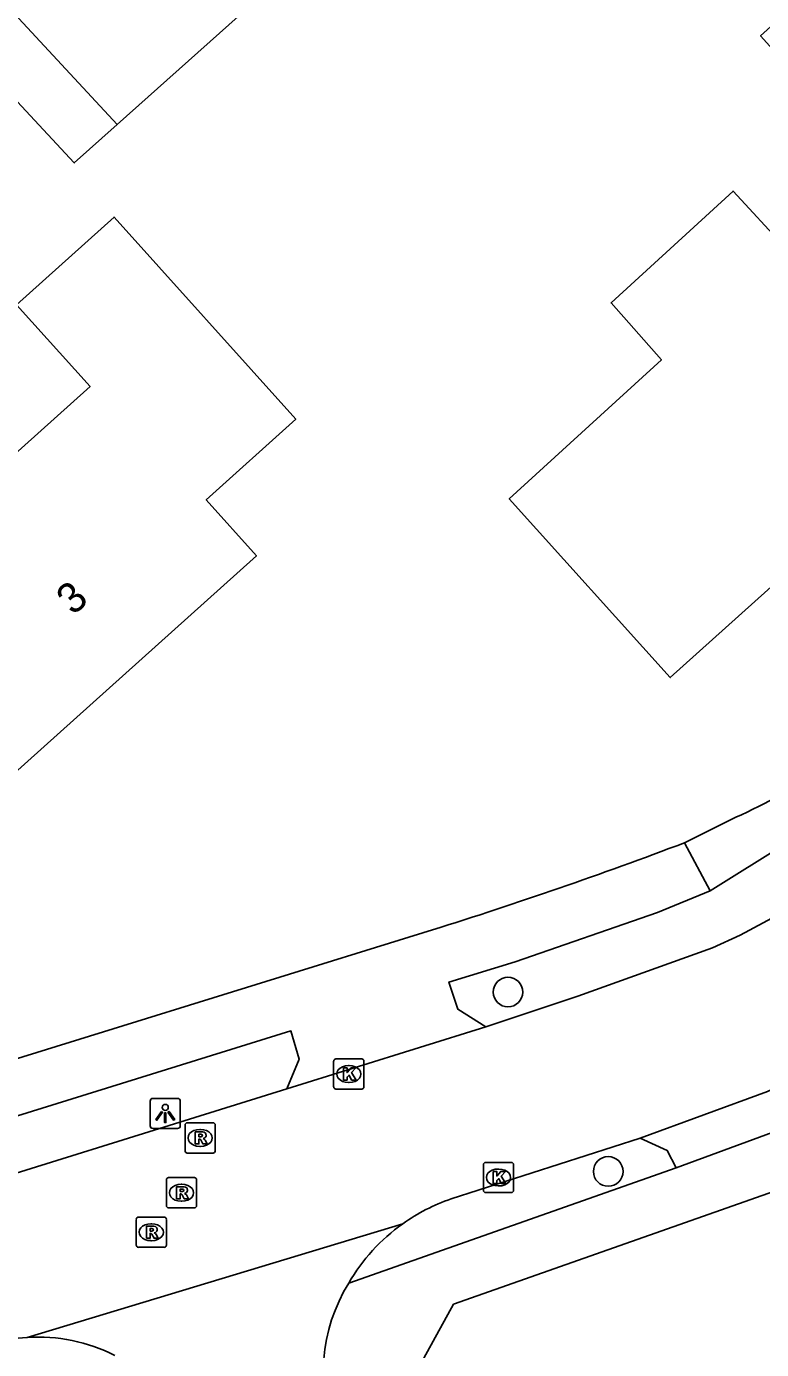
# Model space of a CAD drawing. Extents: x 163268 to 164360, y 381529 to 382285.
# Drawn here: x 163878.84 to 163903.13, y 381641.5 to 381685.27 of the extents above; entities that cross this region are included whole.
import ezdxf

# ---------------------------------------------------------------- set-up
doc = ezdxf.new("R2010")
doc.units = 0
for name, color, linetype in [('IMGEO_Boom', 7, 'Continuous'), ('IMGEO_Erf', 7, 'Continuous'), ('IMGEO_Hek', 7, 'Continuous'), ('IMGEO_Kolk', 7, 'Continuous'), ('IMGEO_Lichtpunt', 7, 'Continuous'), ('IMGEO_Pand', 7, 'Continuous'), ('IMGEO_Pand_nummerreeks', 7, 'Continuous'), ('IMGEO_Rijbaan_lokaal_open', 7, 'Continuous'), ('IMGEO_Rioolput', 7, 'Continuous'), ('IMGEO_Voetpad_open', 7, 'Continuous')]:
    doc.layers.add(name, color=color, linetype=linetype)

msp = doc.modelspace()

# ---------------------------------------------------------------- linework, layer by layer
at = {"layer": 'IMGEO_Boom'}
for centre in [(163894.752, 381653.329), (163898.065, 381647.395)]:
    msp.add_circle(centre, 0.489, dxfattribs=at)
at = {"layer": 'IMGEO_Erf'}
msp.add_lwpolyline([(163881.763, 381723.722), (163902.744, 381700.712), (163881.837, 381682.029), (163880.414, 381680.758), (163874.024, 381687.636), (163866.027, 381679.982), (163845.156, 381661.33)], dxfattribs=at)
at = {"layer": 'IMGEO_Hek'}
for points in [[(163902.744, 381700.712), (163881.837, 381682.029)], [(163881.837, 381682.029), (163874.606, 381689.824), (163846.633, 381663.876), (163845.156, 381661.33)]]:
    msp.add_lwpolyline(points, dxfattribs=at)
at = {"layer": 'IMGEO_Kolk'}
for p, q in [((163888.99, 381650.191), (163888.99, 381651.043)), ((163889.065, 381651.117), (163889.917, 381651.117)), ((163889.991, 381651.043), (163889.991, 381650.191)), ((163889.478, 381650.897), (163889.503, 381650.897)), ((163889.917, 381650.117), (163889.065, 381650.117)), ((163889.501, 381650.337), (163889.476, 381650.337)), ((163893.937, 381646.769), (163893.937, 381647.621)), ((163894.012, 381647.695), (163894.864, 381647.695)), ((163894.425, 381647.475), (163894.45, 381647.475)), ((163894.938, 381647.621), (163894.938, 381646.769)), ((163894.864, 381646.695), (163894.012, 381646.695)), ((163894.448, 381646.915), (163894.423, 381646.915))]:
    msp.add_line(p, q, dxfattribs=at)
for points in [[(163888.99, 381650.191), (163888.99, 381651.043)], [(163889.065, 381651.117), (163889.917, 381651.117)], [(163889.991, 381651.043), (163889.991, 381650.191)], [(163889.311, 381650.817), (163889.434, 381650.817), (163889.434, 381650.666), (163889.564, 381650.817), (163889.728, 381650.817), (163889.582, 381650.666), (163889.735, 381650.417), (163889.583, 381650.417), (163889.498, 381650.581), (163889.434, 381650.514), (163889.434, 381650.417), (163889.311, 381650.417), (163889.311, 381650.817)], [(163889.917, 381650.117), (163889.065, 381650.117)], [(163893.937, 381646.769), (163893.937, 381647.621)], [(163894.012, 381647.695), (163894.864, 381647.695)], [(163894.938, 381647.621), (163894.938, 381646.769)], [(163894.258, 381647.395), (163894.381, 381647.395), (163894.381, 381647.244), (163894.511, 381647.395), (163894.675, 381647.395), (163894.529, 381647.244), (163894.682, 381646.995), (163894.53, 381646.995), (163894.445, 381647.159), (163894.381, 381647.092), (163894.381, 381646.995), (163894.258, 381646.995), (163894.258, 381647.395)], [(163894.864, 381646.695), (163894.012, 381646.695)]]:
    msp.add_lwpolyline(points, dxfattribs=at)
for centre, start, end in [((163889.067, 381651.041), 91.552, 178.448), ((163889.067, 381651.041), 91.552, 178.448), ((163889.915, 381651.041), 1.552, 88.448), ((163889.915, 381651.041), 1.552, 88.448), ((163889.067, 381650.193), 181.552, 268.448), ((163889.067, 381650.193), 181.552, 268.448), ((163889.915, 381650.193), 271.552, 358.448), ((163889.915, 381650.193), 271.552, 358.448), ((163894.014, 381647.619), 91.552, 178.448), ((163894.014, 381647.619), 91.552, 178.448), ((163894.862, 381647.619), 1.552, 88.448), ((163894.862, 381647.619), 1.552, 88.448), ((163894.014, 381646.771), 181.552, 268.448), ((163894.014, 381646.771), 181.552, 268.448), ((163894.862, 381646.771), 271.552, 358.448), ((163894.862, 381646.771), 271.552, 358.448)]:
    msp.add_arc(centre, 0.0765, start, end, dxfattribs=at)
for centre, major_axis, ratio, start_param, end_param in [((163889.477, 381650.617), (-0.387, 0.002), 0.722429, 4.712389, 7.853982), ((163889.502, 381650.617), (-0.39, 0.002), 0.717154, 1.570796, 4.712389), ((163894.424, 381647.195), (-0.387, 0.002), 0.722429, 4.712389, 7.853982), ((163894.449, 381647.195), (-0.39, 0.002), 0.717154, 1.570796, 4.712389)]:
    msp.add_ellipse(centre, major_axis=major_axis, ratio=ratio, start_param=start_param, end_param=end_param, dxfattribs=at)
at = {"layer": 'IMGEO_Lichtpunt'}
for p, q in [((163882.925, 381649.716), (163882.925, 381648.909)), ((163882.925, 381649.716), (163882.925, 381648.909)), ((163883.827, 381649.811), (163883.019, 381649.811)), ((163883.827, 381649.811), (163883.019, 381649.811)), ((163883.921, 381648.909), (163883.921, 381649.716)), ((163883.921, 381648.909), (163883.921, 381649.716)), ((163883.019, 381648.815), (163883.827, 381648.815)), ((163883.019, 381648.815), (163883.827, 381648.815))]:
    msp.add_line(p, q, dxfattribs=at)
for points in [[(163883.299, 381649.38), (163883.338, 381649.352), (163883.15, 381649.09), (163883.112, 381649.117), (163883.299, 381649.38)], [(163883.401, 381649.332), (163883.448, 381649.332), (163883.448, 381649.01), (163883.401, 381649.01), (163883.401, 381649.332)], [(163883.511, 381649.352), (163883.549, 381649.379), (163883.736, 381649.117), (163883.697, 381649.089), (163883.511, 381649.352)]]:
    msp.add_lwpolyline(points, dxfattribs=at)
msp.add_circle((163883.424, 381649.514), 0.0994, dxfattribs=at)
for centre, start, end in [((163883.019, 381649.716), 90, 180), ((163883.019, 381649.716), 90, 180), ((163883.827, 381649.716), 0, 90), ((163883.827, 381649.716), 0, 90), ((163883.019, 381648.909), 180, 270), ((163883.019, 381648.909), 180, 270), ((163883.827, 381648.909), 270, 0), ((163883.827, 381648.909), 270, 360)]:
    msp.add_arc(centre, 0.0946, start, end, dxfattribs=at)
at = {"layer": 'IMGEO_Pand'}
for points in [[(163910.845, 381685.239), (163911.326, 381685.672), (163917.227, 381679.103), (163900.114, 381663.732), (163894.791, 381669.649), (163899.822, 381674.244), (163898.16, 381676.126), (163902.193, 381679.825), (163903.898, 381677.967), (163906.916, 381680.724), (163903.102, 381684.959), (163907.494, 381688.938), (163910.845, 381685.239)], [(163872.768, 381668.141), (163872.211, 381667.639), (163873.261, 381666.473), (163880.938, 381673.363), (163878.509, 381676.061), (163881.732, 381678.963), (163887.739, 381672.277), (163884.777, 381669.606), (163886.436, 381667.762), (163878.235, 381660.379), (163876.574, 381662.222), (163867.219, 381653.819), (163861.224, 381660.52), (163870.832, 381669.17), (163870.966, 381669.022), (163871.524, 381669.524), (163872.768, 381668.141)]]:
    msp.add_lwpolyline(points, dxfattribs=at)
at = {"layer": 'IMGEO_Rijbaan_lokaal_open'}
for points in [[(163909.942, 381659.876), (163907.748, 381658.343), (163906.099, 381657.289), (163903.641, 381655.862), (163902.422, 381655.214), (163901.509, 381654.797), (163897.063, 381653.193), (163894.024, 381652.181)], [(163894.024, 381652.181), (163887.447, 381650.131)], [(163899.123, 381648.496), (163903.327, 381650.044), (163904.788, 381650.707)], [(163887.447, 381650.131), (163874.425, 381646.069), (163872.764, 381645.681), (163871.284, 381645.445), (163869.713, 381645.304), (163867.999, 381645.264), (163866.089, 381645.401), (163864.431, 381645.644), (163862.62, 381646.056), (163861.271, 381646.469), (163859.824, 381647.022)], [(163892.869, 381646.488), (163899.123, 381648.496)], [(163878.855, 381641.903), (163891.273, 381645.664)]]:
    msp.add_lwpolyline(points, dxfattribs=at)
for centre, radius, start, end in [((163894.889, 381640.617), 6.208, 108.9896, 125.6242), ((163894.9, 381640.57), 6.253, 125.4513, 149.9549), ((163894.265, 381640.748), 5.617, 148.2815, 202.8015), ((163879.223, 381636.493), 5.423, 93.8905, 106.2449), ((163879.239, 381636.405), 5.512, 62.8488, 93.9921)]:
    msp.add_arc(centre, radius, start, end, dxfattribs=at)
at = {"layer": 'IMGEO_Rioolput'}
for p, q in [((163884.077, 381648.079), (163884.077, 381648.931)), ((163884.152, 381649.005), (163885.004, 381649.005)), ((163884.565, 381648.785), (163884.59, 381648.785)), ((163885.078, 381648.931), (163885.078, 381648.079)), ((163885.004, 381648.005), (163884.152, 381648.005)), ((163884.588, 381648.225), (163884.563, 381648.225)), ((163883.46, 381646.265), (163883.46, 381647.117)), ((163883.535, 381647.191), (163884.387, 381647.191)), ((163883.948, 381646.971), (163883.973, 381646.971)), ((163884.461, 381647.117), (163884.461, 381646.265)), ((163884.387, 381646.191), (163883.535, 381646.191)), ((163883.971, 381646.411), (163883.946, 381646.411)), ((163882.462, 381644.959), (163882.462, 381645.811)), ((163882.537, 381645.885), (163883.389, 381645.885)), ((163882.95, 381645.665), (163882.975, 381645.665)), ((163883.463, 381645.811), (163883.463, 381644.959)), ((163883.389, 381644.885), (163882.537, 381644.885)), ((163882.973, 381645.105), (163882.948, 381645.105))]:
    msp.add_line(p, q, dxfattribs=at)
for points in [[(163884.077, 381648.079), (163884.077, 381648.931)], [(163884.152, 381649.005), (163885.004, 381649.005)], [(163885.078, 381648.931), (163885.078, 381648.079)], [(163884.666, 381648.703), (163884.414, 381648.705), (163884.414, 381648.305)], [(163884.414, 381648.305), (163884.538, 381648.305), (163884.538, 381648.467), (163884.549, 381648.467)], [(163884.592, 381648.624), (163884.538, 381648.624), (163884.538, 381648.543)], [(163884.538, 381648.543), (163884.59, 381648.543)], [(163884.596, 381648.438), (163884.667, 381648.305), (163884.807, 381648.305), (163884.742, 381648.431)], [(163885.004, 381648.005), (163884.152, 381648.005)], [(163883.46, 381646.265), (163883.46, 381647.117)], [(163883.535, 381647.191), (163884.387, 381647.191)], [(163884.461, 381647.117), (163884.461, 381646.265)], [(163884.049, 381646.889), (163883.797, 381646.891), (163883.797, 381646.491)], [(163883.797, 381646.491), (163883.921, 381646.491), (163883.921, 381646.653), (163883.932, 381646.653)], [(163883.975, 381646.81), (163883.921, 381646.81), (163883.921, 381646.729)], [(163883.921, 381646.729), (163883.973, 381646.729)], [(163883.979, 381646.624), (163884.05, 381646.491), (163884.19, 381646.491), (163884.125, 381646.617)], [(163884.387, 381646.191), (163883.535, 381646.191)], [(163882.462, 381644.959), (163882.462, 381645.811)], [(163882.537, 381645.885), (163883.389, 381645.885)], [(163883.463, 381645.811), (163883.463, 381644.959)], [(163883.051, 381645.583), (163882.799, 381645.585), (163882.799, 381645.185)], [(163882.799, 381645.185), (163882.923, 381645.185), (163882.923, 381645.347), (163882.934, 381645.347)], [(163882.977, 381645.504), (163882.923, 381645.504), (163882.923, 381645.423)], [(163882.923, 381645.423), (163882.975, 381645.423)], [(163882.981, 381645.318), (163883.052, 381645.185), (163883.192, 381645.185), (163883.127, 381645.311)], [(163883.389, 381644.885), (163882.537, 381644.885)]]:
    msp.add_lwpolyline(points, dxfattribs=at)
for centre, radius, start, end in [((163884.154, 381648.929), 0.0765, 91.552, 178.448), ((163884.154, 381648.929), 0.0765, 91.552, 178.448), ((163885.002, 381648.929), 0.0765, 1.552, 88.448), ((163885.002, 381648.929), 0.0765, 1.552, 88.448), ((163884.548, 381648.414), 0.0533, 26.0293, 88.6989), ((163884.574, 381648.732), 0.19, 274.7715, 282.9687), ((163884.598, 381648.528), 0.0964, 77.0061, 93.1865), ((163884.612, 381648.585), 0.0378, 276.6634, 79.6772), ((163884.665, 381648.593), 0.109, 350.3612, 89.416), ((163884.663, 381648.593), 0.112, 277.5842, 350.9817), ((163884.647, 381648.378), 0.108, 29.5134, 73.7905), ((163884.154, 381648.081), 0.0765, 181.552, 268.448), ((163884.154, 381648.081), 0.0765, 181.552, 268.448), ((163885.002, 381648.081), 0.0765, 271.552, 358.448), ((163885.002, 381648.081), 0.0765, 271.552, 358.448), ((163883.537, 381647.115), 0.0765, 91.552, 178.448), ((163883.537, 381647.115), 0.0765, 91.552, 178.448), ((163884.385, 381647.115), 0.0765, 1.552, 88.448), ((163884.385, 381647.115), 0.0765, 1.552, 88.448), ((163883.931, 381646.6), 0.0533, 26.0293, 88.6989), ((163883.957, 381646.918), 0.19, 274.7715, 282.9687), ((163883.981, 381646.714), 0.0964, 77.0061, 93.1865), ((163883.995, 381646.771), 0.0378, 276.6634, 79.6772), ((163884.048, 381646.779), 0.109, 350.3612, 89.416), ((163884.046, 381646.779), 0.112, 277.5842, 350.9817), ((163884.03, 381646.564), 0.108, 29.5134, 73.7905), ((163883.537, 381646.267), 0.0765, 181.552, 268.448), ((163883.537, 381646.267), 0.0765, 181.552, 268.448), ((163884.385, 381646.267), 0.0765, 271.552, 358.448), ((163884.385, 381646.267), 0.0765, 271.552, 358.448), ((163882.539, 381645.809), 0.0765, 91.552, 178.448), ((163882.539, 381645.809), 0.0765, 91.552, 178.448), ((163883.387, 381645.809), 0.0765, 1.552, 88.448), ((163883.387, 381645.809), 0.0765, 1.552, 88.448), ((163882.933, 381645.294), 0.0533, 26.0293, 88.6989), ((163882.959, 381645.612), 0.19, 274.7715, 282.9687), ((163882.983, 381645.408), 0.0964, 77.0061, 93.1865), ((163882.997, 381645.465), 0.0378, 276.6634, 79.6772), ((163883.05, 381645.473), 0.109, 350.3612, 89.416), ((163883.048, 381645.473), 0.112, 277.5842, 350.9817), ((163883.032, 381645.258), 0.108, 29.5134, 73.7905), ((163882.539, 381644.961), 0.0765, 181.552, 268.448), ((163882.539, 381644.961), 0.0765, 181.552, 268.448), ((163883.387, 381644.961), 0.0765, 271.552, 358.448), ((163883.387, 381644.961), 0.0765, 271.552, 358.448)]:
    msp.add_arc(centre, radius, start, end, dxfattribs=at)
for centre, major_axis, ratio, start_param, end_param in [((163884.564, 381648.505), (-0.387, 0.002), 0.722429, 4.712389, 7.853982), ((163884.589, 381648.505), (-0.39, 0.002), 0.717154, 1.570796, 4.712389), ((163883.947, 381646.691), (-0.387, 0.002), 0.722429, 4.712389, 7.853982), ((163883.972, 381646.691), (-0.39, 0.002), 0.717154, 1.570796, 4.712389), ((163882.949, 381645.385), (-0.387, 0.002), 0.722429, 4.712389, 7.853982), ((163882.974, 381645.385), (-0.39, 0.002), 0.717154, 1.570796, 4.712389)]:
    msp.add_ellipse(centre, major_axis=major_axis, ratio=ratio, start_param=start_param, end_param=end_param, dxfattribs=at)
at = {"layer": 'IMGEO_Voetpad_open'}
for points in [[(163901.437, 381656.675), (163908.824, 381661.296), (163909.942, 381659.876)], [(163900.588, 381658.268), (163902.286, 381659.109)], [(163900.588, 381658.268), (163901.437, 381656.675)], [(163901.437, 381656.675), (163899.692, 381655.96), (163894.99, 381654.332), (163892.801, 381653.658), (163893.095, 381652.76), (163894.024, 381652.181)], [(163874.763, 381649.963), (163892.253, 381655.386)], [(163887.447, 381650.131), (163887.849, 381651.111), (163887.578, 381652.044), (163877.042, 381648.771), (163874.147, 381647.878), (163872.282, 381647.448), (163870.067, 381647.164), (163867.358, 381647.136), (163865.246, 381647.357), (163863.144, 381647.796), (163861.915, 381648.16), (163860.5, 381648.682), (163859.824, 381647.022)], [(163904.646, 381649.112), (163900.305, 381647.52)], [(163900.305, 381647.52), (163900.015, 381648.091), (163899.123, 381648.496)], [(163889.487, 381643.701), (163900.305, 381647.52)], [(163890.818, 381639.108), (163892.952, 381643.003), (163905.312, 381647.362), (163905.281, 381647.443)]]:
    msp.add_lwpolyline(points, dxfattribs=at)
for centre, radius, start, end in [((163891.772, 381681.977), 25.169, 294.6909, 309.6896), ((163848.703, 381794.829), 146.085, 287.34415, 290.80363)]:
    msp.add_arc(centre, radius, start, end, dxfattribs=at)

# ---------------------------------------------------------------- texts
at = {"layer": 'IMGEO_Pand_nummerreeks'}
msp.add_text('3', height=1, rotation=41.3748, dxfattribs=at).set_placement((163880.379, 381665.764))

doc.saveas('drawing.dxf')
